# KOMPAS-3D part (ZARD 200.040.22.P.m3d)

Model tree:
1. Поверхность без истории:1
2. Поверхность без истории:2
3. Поверхность без истории:3
4. Поверхность без истории:4
5. Поверхность без истории:5
6. Поверхность без истории:6
7. Поверхность без истории:7
8. Поверхность без истории:8
9. Поверхность без истории:9
10. Поверхность без истории:10
11. Поверхность без истории:11
12. Поверхность без истории:12
13. Поверхность без истории:13
14. Поверхность без истории:14
15. Поверхность без истории:15
16. Поверхность без истории:16
17. Поверхность без истории:17
18. Поверхность без истории:18
19. Поверхность без истории:19
20. Поверхность без истории:20
21. Поверхность без истории:21
22. Поверхность без истории:22
23. Поверхность без истории:23
24. Поверхность без истории:24
25. Поверхность без истории:25
26. Поверхность без истории:26
27. Поверхность без истории:27
28. Поверхность без истории:28
29. Поверхность без истории:29
30. Поверхность без истории:30
31. Поверхность без истории:31
32. Поверхность без истории:32
33. Поверхность без истории:33
34. Поверхность без истории:34
35. Поверхность без истории:35
36. Поверхность без истории:36
37. Поверхность без истории:37
38. Поверхность без истории:38
39. Поверхность без истории:39
40. Поверхность без истории:40
41. Поверхность без истории:41
42. Поверхность без истории:42
43. Поверхность без истории:43
44. Поверхность без истории:44
45. Поверхность без истории:45
46. Поверхность без истории:46
47. Поверхность без истории:47
48. Поверхность без истории:48
49. Поверхность без истории:49
50. Поверхность без истории:50
51. Поверхность без истории:51
52. Поверхность без истории:52
53. Поверхность без истории:53
54. Поверхность без истории:54
55. Поверхность без истории:55
56. Поверхность без истории:56
57. Поверхность без истории:57
58. Поверхность без истории:58
59. Поверхность без истории:59
60. Поверхность без истории:60
61. Поверхность без истории:61
62. Поверхность без истории:62
63. Поверхность без истории:63
64. Поверхность без истории:64
65. Поверхность без истории:65
66. Поверхность без истории:66
67. Поверхность без истории:67
68. Поверхность без истории:68
69. Поверхность без истории:69
70. Поверхность без истории:70
71. Поверхность без истории:71
72. Поверхность без истории:72
73. Поверхность без истории:73
74. Поверхность без истории:74
75. Поверхность без истории:75
76. Поверхность без истории:76
77. Поверхность без истории:77
78. Поверхность без истории:78
79. Поверхность без истории:79
80. Поверхность без истории:80
81. Поверхность без истории:81
82. Поверхность без истории:82
83. Поверхность без истории:83
84. Поверхность без истории:84
85. Поверхность без истории:85
86. Поверхность без истории:86
87. Поверхность без истории:87
88. Поверхность без истории:88
89. Поверхность без истории:89
90. Поверхность без истории:90
91. Поверхность без истории:91
92. Поверхность без истории:92
93. Поверхность без истории:93
94. Поверхность без истории:94
95. Поверхность без истории:95
96. Поверхность без истории:96
97. Поверхность без истории:97
98. Поверхность без истории:98
99. Поверхность без истории:99
100. Поверхность без истории:100
101. Поверхность без истории:101
102. Поверхность без истории:102
103. Поверхность без истории:103

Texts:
  ЗАРД 200-040-22-Р(АВ880) КП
